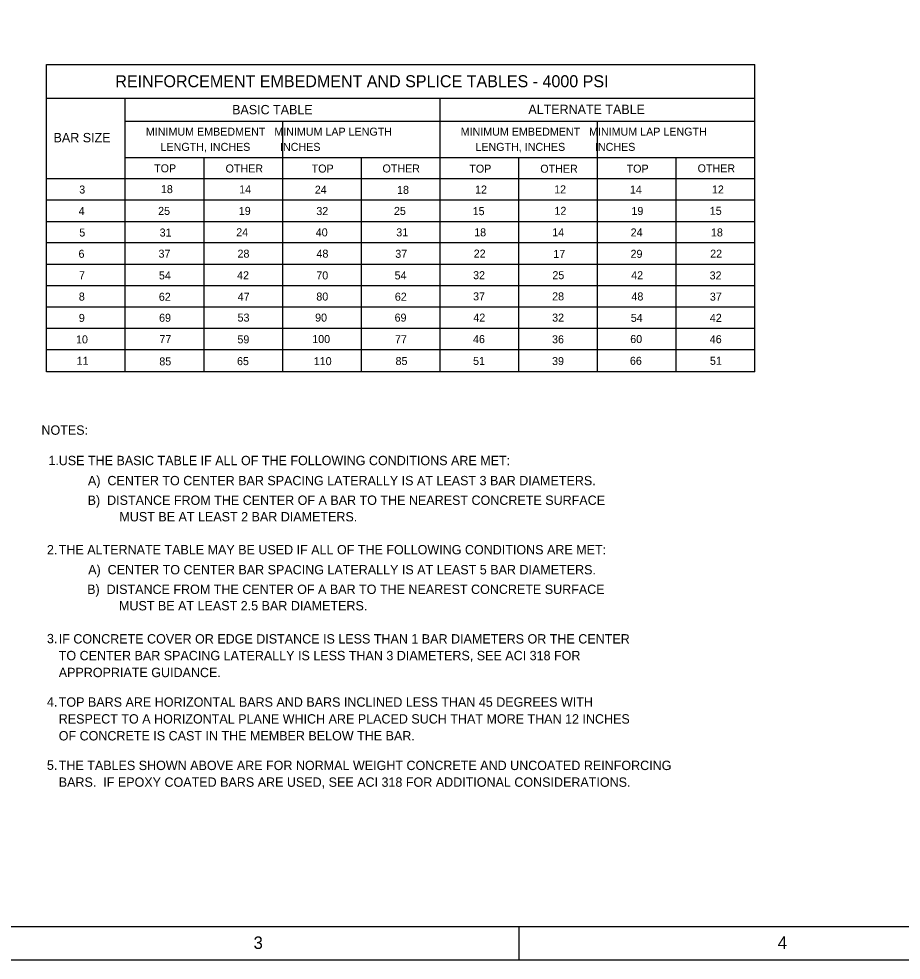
# Model space of a CAD drawing. Extents: x 22369.62 to 22373.29, y 22369.62 to 22372.46.
# Drawn here: x 22371.083 to 22372.185, y 22369.621 to 22370.797 of the extents above; entities that cross this region are included whole.
import ezdxf

# ---------------------------------------------------------------- set-up
doc = ezdxf.new("R2010")
doc.units = 0
for name, color, linetype in [('Level 1', 7, 'Continuous'), ('Level 10', 7, 'Continuous'), ('Level 2', 7, 'Continuous'), ('Level 4', 7, 'Continuous'), ('Level 7', 7, 'Continuous'), ('Level 9', 7, 'Continuous')]:
    doc.layers.add(name, color=color, linetype=linetype)

msp = doc.modelspace()

# ---------------------------------------------------------------- linework, layer by layer
at = {"layer": 'Level 1'}
for p, q in [((22372.0026, 22370.5708), (22371.117, 22370.5708)), ((22372.0026, 22370.5439), (22371.117, 22370.5439)), ((22372.0026, 22370.5173), (22371.117, 22370.5173)), ((22372.0026, 22370.4905), (22371.117, 22370.4905)), ((22372.0026, 22370.4637), (22371.117, 22370.4637)), ((22372.0026, 22370.4372), (22371.117, 22370.4372)), ((22372.0026, 22370.4106), (22371.117, 22370.4106)), ((22372.0026, 22370.3838), (22371.117, 22370.3838))]:
    msp.add_line(p, q, dxfattribs=at)
msp.add_lwpolyline([(22369.6213, 22372.4553), (22373.288, 22372.4553), (22373.288, 22369.6213), (22369.6213, 22369.6213)], close=True, dxfattribs=at)
at = {"layer": 'Level 10'}
for p, q in [((22371.117, 22370.3564), (22371.117, 22370.7402)), ((22371.117, 22370.7402), (22372.0026, 22370.7402)), ((22372.0026, 22370.3564), (22372.0026, 22370.7402)), ((22371.117, 22370.6984), (22372.0026, 22370.6984)), ((22372.0026, 22370.3564), (22371.117, 22370.3564)), ((22371.708, 22369.6213), (22371.708, 22369.6633))]:
    msp.add_line(p, q, dxfattribs=at)
at = {"layer": 'Level 2'}
for p, q in [((22371.3141, 22370.3564), (22371.3141, 22370.6241)), ((22371.5109, 22370.3564), (22371.5109, 22370.6241)), ((22371.7076, 22370.3564), (22371.7076, 22370.6241)), ((22371.9043, 22370.3564), (22371.9043, 22370.6241))]:
    msp.add_line(p, q, dxfattribs=at)
at = {"layer": 'Level 7'}
for p, q in [((22371.2157, 22370.3564), (22371.2157, 22370.6984)), ((22371.6093, 22370.3564), (22371.6093, 22370.6984)), ((22371.2157, 22370.6697), (22372.0026, 22370.6697)), ((22371.4125, 22370.3564), (22371.4125, 22370.6697)), ((22371.8059, 22370.3564), (22371.8059, 22370.6697)), ((22371.2157, 22370.6241), (22372.0026, 22370.6241)), ((22372.0026, 22370.5973), (22371.117, 22370.5973))]:
    msp.add_line(p, q, dxfattribs=at)
at = {"layer": 'Level 9'}
msp.add_line((22369.7463, 22369.6633), (22373.017, 22369.6633), dxfattribs=at)

# ---------------------------------------------------------------- texts
at = {"layer": 'Level 1'}
for s, p in [('3', (22371.376, 22369.6353)), ('4', (22372.031, 22369.6353))]:
    msp.add_text(s, height=0.0156, dxfattribs=at).set_placement(p)
at = {"layer": 'Level 4'}
for s, height, p in [('REINFORCEMENT EMBEDMENT AND SPLICE TABLES - 4000 PSI', 0.015, (22371.2032, 22370.7119)), ('BASIC TABLE', 0.011667, (22371.3492, 22370.6781)), ('ALTERNATE TABLE', 0.011667, (22371.7194, 22370.6784)), ('MINIMUM EMBEDMENT   MINIMUM LAP LENGTH', 0.01, (22371.2414, 22370.6514)), ('MINIMUM EMBEDMENT   MINIMUM LAP LENGTH', 0.01, (22371.6348, 22370.6514)), ('BAR SIZE', 0.0117, (22371.126, 22370.6431)), ('LENGTH, INCHES          INCHES', 0.01, (22371.2597, 22370.6324)), ('LENGTH, INCHES          INCHES', 0.01, (22371.6532, 22370.6324)), ('TOP', 0.01, (22371.2517, 22370.6056)), ('OTHER', 0.01, (22371.341, 22370.6054)), ('TOP', 0.01, (22371.4486, 22370.6053)), ('OTHER', 0.01, (22371.5371, 22370.6054)), ('TOP', 0.01, (22371.6456, 22370.6052)), ('OTHER', 0.01, (22371.7343, 22370.6051)), ('TOP', 0.01, (22371.8422, 22370.6052)), ('OTHER', 0.01, (22371.9309, 22370.6056)), ('18', 0.01, (22371.2602, 22370.5796)), ('3', 0.01, (22371.1581, 22370.5791)), ('14', 0.01, (22371.358, 22370.5793)), ('24', 0.01, (22371.4525, 22370.5789)), ('18', 0.01, (22371.5553, 22370.5787)), ('12', 0.01, (22371.6528, 22370.5791)), ('12', 0.01, (22371.7516, 22370.5793)), ('14', 0.01, (22371.8463, 22370.579)), ('12', 0.01, (22371.9488, 22370.5792)), ('4', 0.01, (22371.1574, 22370.5523)), ('25', 0.01, (22371.2567, 22370.5524)), ('19', 0.01, (22371.3575, 22370.5524)), ('32', 0.01, (22371.4544, 22370.5522)), ('25', 0.01, (22371.5514, 22370.5524)), ('15', 0.01, (22371.6498, 22370.5521)), ('12', 0.01, (22371.752, 22370.5525)), ('19', 0.01, (22371.8482, 22370.5523)), ('15', 0.01, (22371.9461, 22370.5525)), ('5', 0.01, (22371.1582, 22370.5254)), ('31', 0.01, (22371.2586, 22370.5254)), ('24', 0.01, (22371.3543, 22370.5257)), ('40', 0.01, (22371.4537, 22370.5256)), ('31', 0.01, (22371.5543, 22370.5256)), ('18', 0.01, (22371.6517, 22370.5256)), ('14', 0.01, (22371.7492, 22370.5256)), ('24', 0.01, (22371.8472, 22370.5255)), ('18', 0.01, (22371.9476, 22370.5255)), ('6', 0.01, (22371.1572, 22370.4988)), ('37', 0.01, (22371.2572, 22370.499)), ('28', 0.01, (22371.3559, 22370.499)), ('48', 0.01, (22371.4546, 22370.499)), ('37', 0.01, (22371.5531, 22370.4988)), ('22', 0.01, (22371.6511, 22370.4991)), ('17', 0.01, (22371.7506, 22370.4987)), ('29', 0.01, (22371.8471, 22370.4988)), ('22', 0.01, (22371.9466, 22370.499)), ('7', 0.01, (22371.1578, 22370.472)), ('54', 0.01, (22371.2577, 22370.4718)), ('42', 0.01, (22371.3554, 22370.472)), ('70', 0.01, (22371.4544, 22370.4718)), ('54', 0.01, (22371.5522, 22370.4718)), ('32', 0.01, (22371.6503, 22370.4721)), ('25', 0.01, (22371.7494, 22370.4721)), ('42', 0.01, (22371.8479, 22370.472)), ('32', 0.01, (22371.9459, 22370.4718)), ('8', 0.01, (22371.1576, 22370.4454)), ('62', 0.01, (22371.2576, 22370.4451)), ('47', 0.01, (22371.3561, 22370.4451)), ('80', 0.01, (22371.4544, 22370.4454)), ('62', 0.01, (22371.5525, 22370.4452)), ('37', 0.01, (22371.6503, 22370.4456)), ('28', 0.01, (22371.7491, 22370.4456)), ('48', 0.01, (22371.8482, 22370.4455)), ('37', 0.01, (22371.9462, 22370.4453)), ('9', 0.01, (22371.1576, 22370.4187)), ('69', 0.01, (22371.2579, 22370.4189)), ('53', 0.01, (22371.356, 22370.4191)), ('90', 0.01, (22371.4529, 22370.4191)), ('69', 0.01, (22371.5522, 22370.4191)), ('42', 0.01, (22371.6506, 22370.4191)), ('32', 0.01, (22371.7491, 22370.4191)), ('54', 0.01, (22371.8474, 22370.4188)), ('42', 0.01, (22371.9462, 22370.4188)), ('10', 0.01, (22371.1541, 22370.3919)), ('77', 0.01, (22371.2583, 22370.3922)), ('59', 0.01, (22371.3558, 22370.3919)), ('100', 0.01, (22371.4493, 22370.3923)), ('77', 0.01, (22371.5527, 22370.3921)), ('46', 0.01, (22371.6502, 22370.3922)), ('36', 0.01, (22371.749, 22370.392)), ('60', 0.01, (22371.8467, 22370.3923)), ('46', 0.01, (22371.9461, 22370.3921)), ('11', 0.01, (22371.1549, 22370.3651)), ('85', 0.01, (22371.2582, 22370.3644)), ('65', 0.01, (22371.3553, 22370.3647)), ('110', 0.01, (22371.4512, 22370.3647)), ('85', 0.01, (22371.5534, 22370.3649)), ('51', 0.01, (22371.6503, 22370.365)), ('39', 0.01, (22371.749, 22370.3648)), ('66', 0.01, (22371.8463, 22370.3651)), ('51', 0.01, (22371.9463, 22370.3651)), ('NOTES:', 0.0117, (22371.1109, 22370.2777)), ('1.', 0.0117, (22371.1197, 22370.2398)), ('  USE THE BASIC TABLE IF ALL OF THE FOLLOWING CONDITIONS ARE MET:', 0.011698, (22371.1238, 22370.2397)), ('A)  CENTER TO CENTER BAR SPACING LATERALLY IS AT LEAST 3 BAR DIAMETERS.', 0.011698, (22371.169, 22370.2146)), ('B)  DISTANCE FROM THE CENTER OF A BAR TO THE NEAREST CONCRETE SURFACE', 0.011698, (22371.1686, 22370.1901)), ('MUST BE AT LEAST 2 BAR DIAMETERS.', 0.011698, (22371.2083, 22370.1695)), ('2.', 0.0117, (22371.1177, 22370.1283)), ('  THE ALTERNATE TABLE MAY BE USED IF ALL OF THE FOLLOWING CONDITIONS ARE MET:', 0.011698, (22371.1238, 22370.1283)), ('A)  CENTER TO CENTER BAR SPACING LATERALLY IS AT LEAST 5 BAR DIAMETERS.', 0.011698, (22371.1693, 22370.1033)), ('B)  DISTANCE FROM THE CENTER OF A BAR TO THE NEAREST CONCRETE SURFACE', 0.011698, (22371.168, 22370.0788)), ('MUST BE AT LEAST 2.5 BAR DIAMETERS.', 0.011698, (22371.2078, 22370.0583)), ('3.', 0.0117, (22371.1177, 22370.0172)), ('  IF CONCRETE COVER OR EDGE DISTANCE IS LESS THAN 1 BAR DIAMETERS OR THE CENTER', 0.011698, (22371.1238, 22370.0169)), ('  TO CENTER BAR SPACING LATERALLY IS LESS THAN 3 DIAMETERS, SEE ACI 318 FOR', 0.011698, (22371.1238, 22369.996)), ('  APPROPRIATE GUIDANCE.', 0.011698, (22371.1238, 22369.9749)), ('4.', 0.0117, (22371.1177, 22369.9381)), ('  TOP BARS ARE HORIZONTAL BARS AND BARS INCLINED LESS THAN 45 DEGREES WITH', 0.011698, (22371.1238, 22369.9379)), ('  RESPECT TO A HORIZONTAL PLANE WHICH ARE PLACED SUCH THAT MORE THAN 12 INCHES', 0.011698, (22371.1238, 22369.9169)), ('  OF CONCRETE IS CAST IN THE MEMBER BELOW THE BAR.', 0.011698, (22371.1238, 22369.8958)), ('5.', 0.0117, (22371.1177, 22369.8591)), ('  THE TABLES SHOWN ABOVE ARE FOR NORMAL WEIGHT CONCRETE AND UNCOATED REINFORCING', 0.011698, (22371.1238, 22369.8588)), ('  BARS.  IF EPOXY COATED BARS ARE USED, SEE ACI 318 FOR ADDITIONAL CONSIDERATIONS.', 0.011698, (22371.1238, 22369.8379))]:
    msp.add_text(s, height=height, dxfattribs=at).set_placement(p)

doc.saveas('drawing.dxf')
